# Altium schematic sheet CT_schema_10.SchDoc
size 254 x 194 mm
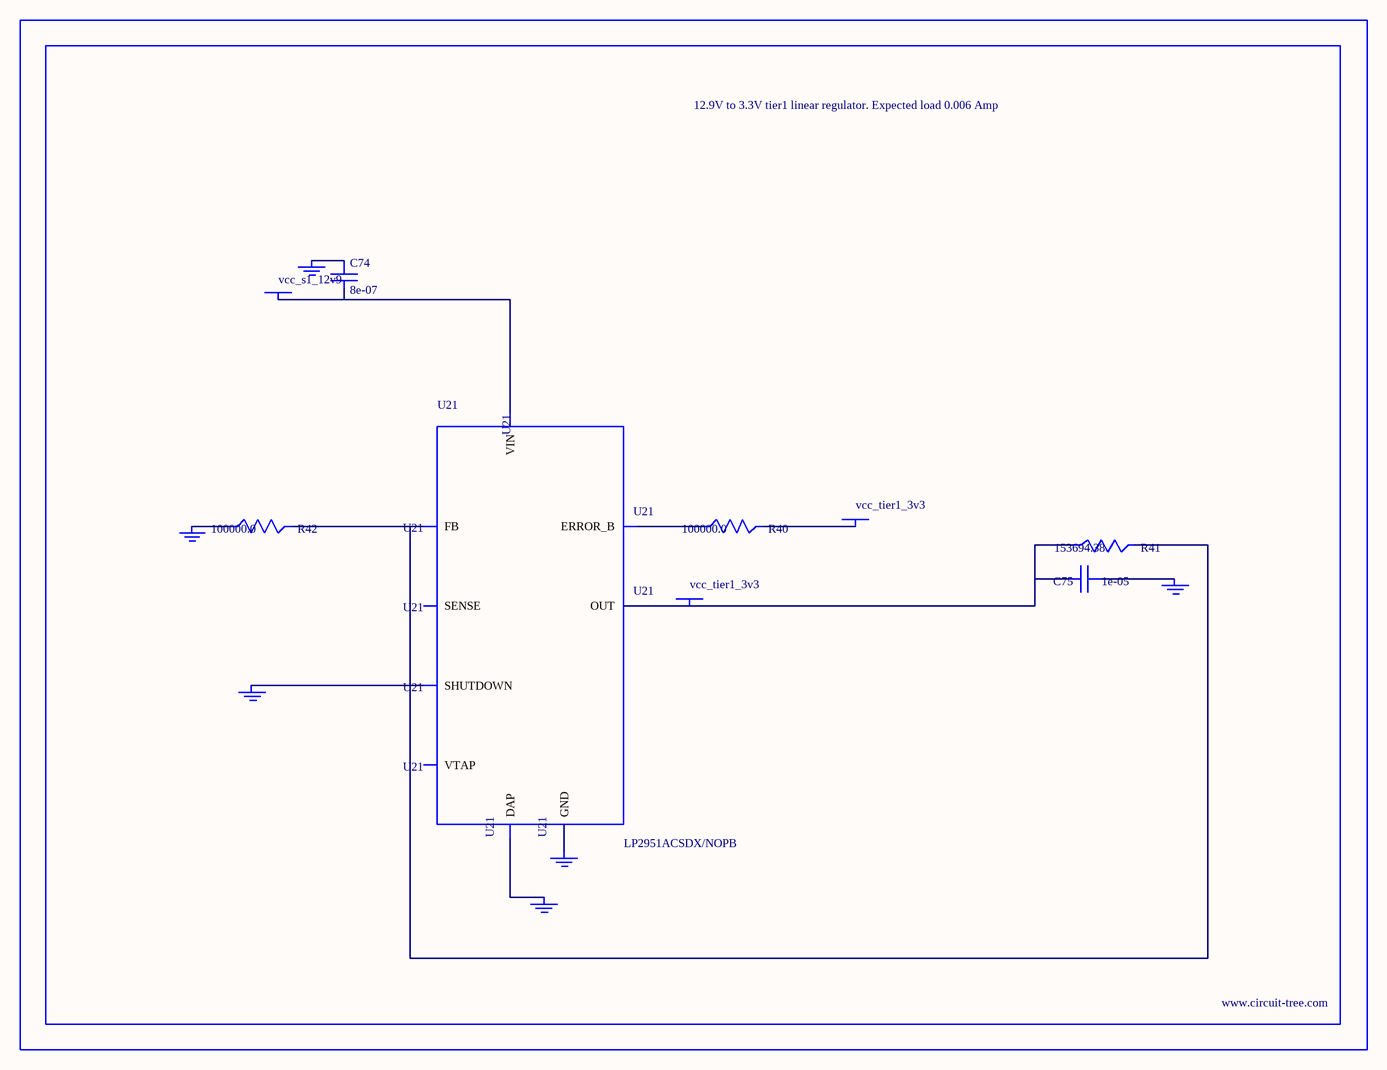
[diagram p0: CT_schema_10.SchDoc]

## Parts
BORDER9  (no value)
C74  8e-07  [R0603]
C75  1e-05  [C1210]
GND_INSTANCE_9_0  (no value)
GND_INSTANCE_9_1  (no value)
GND_INSTANCE_9_2  (no value)
GND_INSTANCE_9_3  (no value)
GND_INSTANCE_9_4  (no value)
GND_INSTANCE_9_5  (no value)
POWER_INSTANCE_9_0  vcc_tier1_3v3
POWER_INSTANCE_9_1  vcc_s1_12v9
POWER_INSTANCE_9_2  vcc_tier1_3v3
R40  100000.0  [R0603]
R41  153694.38  [R0603]
R42  100000.0  [R0603]
U21  LP2951ACSDX/NOPB  [WSON-8]

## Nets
NetC74_1: C74.1 GND_INSTANCE_9_3.0(GND)
NetC74_2: C74.2 POWER_INSTANCE_9_1.0(PWR) U21.8(VIN)
NetC75_1: C75.1 GND_INSTANCE_9_0.0(GND)
NetC75_2: C75.2 POWER_INSTANCE_9_2.0(PWR) R41.1 U21.1(OUT)
NetGND_INSTANCE_9_1_0: GND_INSTANCE_9_1.0(GND) U21.3(SHUTDOWN)
NetGND_INSTANCE_9_2_0: GND_INSTANCE_9_2.0(GND) R42.1
NetGND_INSTANCE_9_4_0: GND_INSTANCE_9_4.0(GND) U21.PAD(DAP)
NetGND_INSTANCE_9_5_0: GND_INSTANCE_9_5.0(GND) U21.4(GND)
NetPOWER_INSTANCE_9_0_0: POWER_INSTANCE_9_0.0(PWR) R40.2
NetR40_1: R40.1 U21.5(ERROR_B)
NetR41_2: R41.2 R42.2 U21.7(FB)

Not connected (* = marked no-connect by the designer): U21 2(SENSE) 6(VTAP)

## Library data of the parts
BORDER9 = BORDER_PAGE9
C74 = C74
C75 = GRM32DR61E106MA12L
GND_INSTANCE_9_0-GND_INSTANCE_9_5 = GND
POWER_INSTANCE_9_0-POWER_INSTANCE_9_2 = PWR
R40 R42 = RC0603JR-07100KL
R41 = R41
